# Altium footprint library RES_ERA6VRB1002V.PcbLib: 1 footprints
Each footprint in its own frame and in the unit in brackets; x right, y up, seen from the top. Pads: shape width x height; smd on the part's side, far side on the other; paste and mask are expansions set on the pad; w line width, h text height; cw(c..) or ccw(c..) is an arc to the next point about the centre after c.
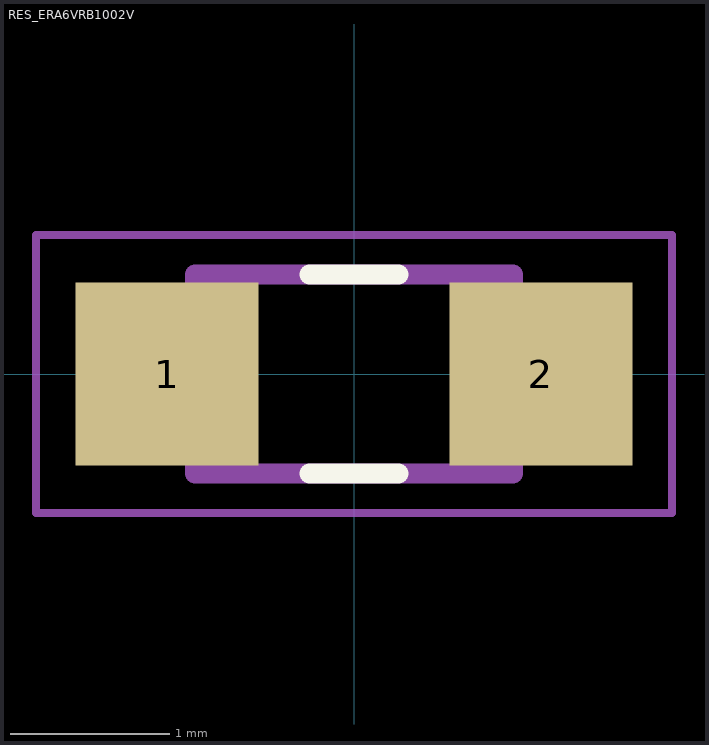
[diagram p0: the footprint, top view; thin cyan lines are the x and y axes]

## RES_ERA6VRB1002V [mm]
pads (2):
  rect 1.15x1.15 smd: 1(-1.175,0) 2(1.175,0)
Top Overlay:
  lines w0.127: -0.28,-0.625 0.28,-0.625 ; -0.28,0.625 0.28,0.625
Mechanical 13:
  lines w0.127: -1,-0.625 -1,0.625 1,0.625 1,-0.625 -1,-0.625
Mechanical 15:
  lines w0.05: -2,-0.875 -2,0.875 2,0.875 2,-0.875 -2,-0.875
